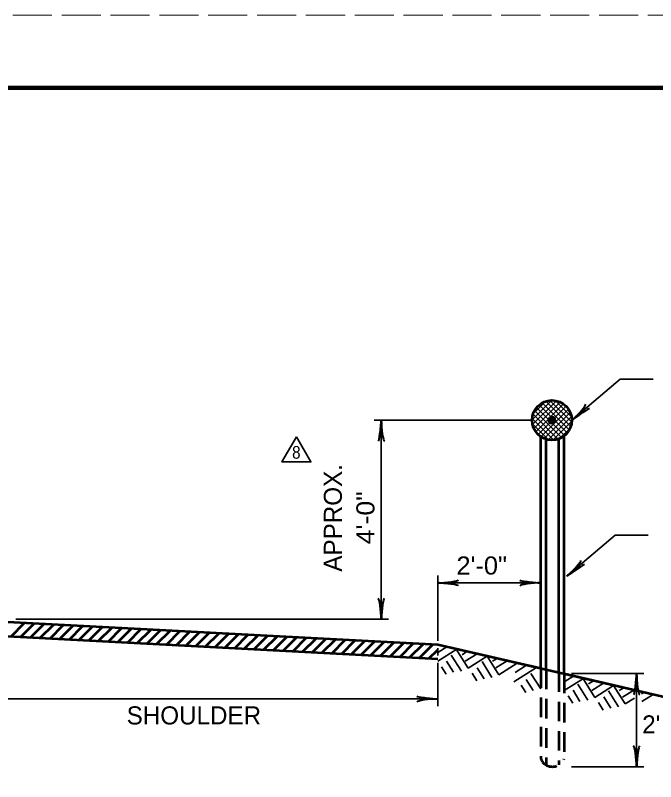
# Model space of a CAD drawing. Extents: x -54 to 626, y -41 to 399.
# Drawn here: x 87.7 to 176.2, y 292.9 to 398.7 of the extents above; entities that cross this region are included whole.
import ezdxf
from ezdxf.enums import TextEntityAlignment as Align

# ---------------------------------------------------------------- set-up
doc = ezdxf.new("R2010")
doc.units = 0
doc.header["$LTSCALE"] = 0.9
doc.linetypes.add('LONG_DASHED', pattern=[7.5, 6, -1.5])
doc.linetypes.add('MEDIUM_DASHED', pattern=[4.5, 3, -1.5])
doc.layers.add('1', color=7, linetype='Continuous', lineweight=35)
doc.layers.add('61', color=7, linetype='Continuous', lineweight=35)

msp = doc.modelspace()

# ---------------------------------------------------------------- hatches: boundary and pattern name
at = {"layer": '1'}
msp.add_hatch(color=256, dxfattribs=at).paths.add_polyline_path([(162.4069, 342.7923, 1), (161.4069, 342.7923, 1)])

# ---------------------------------------------------------------- linework, layer by layer
for p, q in [((159.1578, 342.8207), (161.8773, 345.5402)), ((159.2272, 342.1829), (162.5155, 345.4712)), ((159.3081, 343.6781), (161.022, 345.392)), ((159.4078, 341.6565), (163.0427, 345.2913)), ((159.664, 341.2056), (163.4944, 345.036)), ((164.3008, 341.4444), (160.5599, 345.1853)), ((164.5153, 341.937), (161.0512, 345.4011)), ((164.6395, 342.52), (161.6333, 345.5261)), ((164.6131, 343.2534), (162.3679, 345.4987)), ((163.2352, 340.3887), (159.5023, 344.1216)), ((163.6562, 340.6747), (159.7901, 344.5409)), ((159.9912, 340.8257), (163.8733, 344.7078)), ((164.0105, 341.0276), (160.1414, 344.8967)), ((160.3808, 340.5082), (164.1917, 344.3191)), ((163.9937, 344.58), (163.6965, 344.8772)), ((162.1532, 340.0565), (159.1721, 343.0376)), ((162.7403, 340.1766), (159.2914, 343.6254)), ((160.841, 340.2612), (164.4375, 343.8578)), ((161.3843, 340.0975), (164.6018, 343.315)), ((159.1569, 342.7923), (137.3158, 342.7923)), ((138.3158, 315.3082), (138.3158, 342.7923)), ((161.41, 340.0926), (159.2072, 342.2953)), ((162.0447, 340.0507), (164.6491, 342.6552)), ((162.9561, 340.255), (164.4476, 341.7465)), ((163.9707, 321.2404), (170.6446, 326.9158)), ((170.6446, 326.9158), (175.1863, 326.9158)), ((146.1192, 312.3259), (146.1192, 321.3259)), ((146.1192, 320.3259), (160.3523, 320.3259)), ((87.8158, 315.3082), (139.3158, 315.3082)), ((147.3964, 311.49), (146.1192, 310.6919)), ((146.1192, 311.3259), (146.1192, 310.3044)), ((148.78, 311.1706), (146.1192, 309.508)), ((148.6826, 311.1931), (150.3312, 308.5545)), ((147.9989, 310.3657), (149.3973, 308.1544)), ((150.1636, 310.8511), (149.4875, 310.4119)), ((151.5667, 310.5272), (149.9117, 309.493)), ((152.9503, 310.2077), (150.3312, 308.5545)), ((152.9503, 310.2077), (154.5541, 307.6412)), ((146.1192, 309.3044), (146.1192, 303.3044)), ((147.3347, 309.5337), (148.294, 307.9986)), ((152.2412, 309.4477), (153.6201, 307.241)), ((154.3339, 309.8882), (153.7103, 309.4986)), ((155.737, 309.5643), (154.1539, 308.5752)), ((157.1206, 309.2449), (154.5541, 307.6412)), ((146.6406, 308.7498), (147.2896, 307.7378)), ((151.577, 308.6158), (152.5362, 307.0807)), ((159.7904, 308.6285), (156.6482, 306.6651)), ((158.4067, 308.948), (156.8237, 307.9588)), ((150.8634, 307.8364), (151.5078, 306.805)), ((158.3451, 306.9917), (159.3043, 305.4566)), ((159.0093, 307.8236), (160.3523, 305.6998)), ((164.8795, 307.4537), (163.6023, 306.6556)), ((166.2631, 307.1343), (163.6023, 305.4716)), ((164.6023, 307.7896), (174.6023, 307.7896)), ((166.1657, 307.1567), (167.8144, 304.5182)), ((173.6023, 307.7896), (173.6023, 294.9441)), ((157.651, 306.2077), (158.3, 305.1958)), ((165.482, 306.3293), (166.8804, 304.1181)), ((167.6467, 306.8148), (166.9706, 306.3757)), ((169.0498, 306.4908), (167.3947, 305.4567)), ((170.4334, 306.1714), (167.8144, 304.5182)), ((170.4334, 306.1714), (172.0372, 303.6049)), ((171.817, 305.852), (171.1933, 305.4623)), ((164.8178, 305.4974), (165.7771, 303.9622)), ((169.7242, 305.4115), (171.1033, 303.2047)), ((173.2201, 305.5281), (171.637, 304.5388)), ((174.6037, 305.2087), (174.2584, 304.9929)), ((175.8899, 304.9117), (174.3067, 303.9225)), ((79.3158, 304.3044), (146.1192, 304.3044)), ((164.1238, 304.7134), (164.7728, 303.7015)), ((168.3465, 303.8001), (168.991, 302.7687)), ((169.0601, 304.5796), (170.0193, 303.0444)), ((173.3297, 304.4127), (172.0372, 303.6049)), ((164.6023, 294.9441), (174.6023, 294.9441))]:
    msp.add_line(p, q, dxfattribs=at)
at = {"layer": '1', "lineweight": 53}
for p, q in [((160.3523, 308.5399), (160.3523, 340.5239)), ((161.1023, 308.3667), (161.1023, 340.1627)), ((162.8523, 307.9627), (162.8523, 340.2099)), ((163.6023, 307.7896), (163.6023, 340.6272)), ((79.3158, 315.3082), (146.1192, 311.8259)), ((87.1213, 312.8963), (89.0269, 314.802)), ((88.4651, 312.8259), (90.3711, 314.732)), ((89.8088, 312.7555), (91.7152, 314.6619)), ((91.1526, 312.6851), (93.0593, 314.5918)), ((92.4964, 312.6147), (94.4035, 314.5217)), ((93.8402, 312.5442), (95.7477, 314.4517)), ((95.184, 312.4738), (97.0918, 314.3816)), ((146.1192, 309.8044), (79.3158, 313.3054)), ((96.5277, 312.4034), (98.4359, 314.3116)), ((97.8716, 312.3329), (99.7801, 314.2415)), ((99.2153, 312.2625), (101.1243, 314.1714)), ((100.5592, 312.1921), (102.4684, 314.1013)), ((101.9029, 312.1217), (103.8125, 314.0312)), ((103.2467, 312.0512), (105.1567, 313.9613)), ((104.5905, 311.9808), (106.5008, 313.8912)), ((105.9343, 311.9104), (107.845, 313.8211)), ((107.2781, 311.84), (109.1891, 313.751)), ((108.6219, 311.7696), (110.5332, 313.6809)), ((109.9657, 311.6992), (111.8774, 313.6109)), ((111.3094, 311.6287), (113.2216, 313.5408)), ((112.6532, 311.5582), (114.5657, 313.4708)), ((113.997, 311.4878), (115.9098, 313.4007)), ((115.3408, 311.4174), (117.254, 313.3306)), ((116.6846, 311.347), (118.5982, 313.2605)), ((118.0284, 311.2766), (119.9423, 313.1905)), ((119.3722, 311.2062), (121.2864, 313.1204)), ((120.716, 311.1357), (122.6306, 313.0503)), ((122.0597, 311.0653), (123.9748, 312.9803)), ((123.4036, 310.9949), (125.3188, 312.9102)), ((124.7473, 310.9245), (126.663, 312.8402)), ((126.0912, 310.854), (128.0072, 312.7701)), ((127.4349, 310.7836), (129.3513, 312.7)), ((128.7788, 310.7132), (130.6954, 312.6299)), ((130.1225, 310.6427), (132.0396, 312.5598)), ((131.4663, 310.5723), (133.3837, 312.4898)), ((132.8101, 310.5019), (134.7279, 312.4197)), ((134.1538, 310.4315), (136.072, 312.3497)), ((135.4977, 310.3611), (137.4162, 312.2796)), ((136.8414, 310.2907), (138.7603, 312.2095)), ((138.1852, 310.2202), (140.1045, 312.1394)), ((139.529, 310.1498), (141.4486, 312.0694)), ((140.8728, 310.0793), (142.7927, 311.9993)), ((142.2166, 310.0089), (144.1369, 311.9292)), ((143.5604, 309.9385), (145.4811, 311.8592)), ((146.1192, 311.8259), (160.3523, 308.5398)), ((146.1192, 311.8259), (175.8538, 304.9611)), ((144.9042, 309.8681), (146.1192, 311.0832))]:
    msp.add_line(p, q, dxfattribs=at)
at = {"layer": '1', "linetype": 'MEDIUM_DASHED', "lineweight": 53}
for p, q in [((160.3523, 308.5399), (160.3523, 296.0399)), ((161.1023, 308.3667), (161.1023, 295.1782)), ((162.8523, 307.9627), (162.8523, 295.1782)), ((163.6023, 307.7896), (163.6023, 296.0399))]:
    msp.add_line(p, q, dxfattribs=at)
at = {"layer": '1'}
msp.add_lwpolyline([(164.6569, 342.7923), (171.3307, 348.4677), (175.8724, 348.4677)], dxfattribs=at)
msp.add_lwpolyline([(126.5927, 340.5026), (124.5927, 337.0385), (128.5927, 337.0385)], close=True, dxfattribs=at)
at = {"layer": '1', "lineweight": 53}
msp.add_lwpolyline([(163.6023, 307.7896), (175.8538, 304.9611), (207.6092, 297.6296)], dxfattribs=at)
msp.add_circle((161.9069, 342.7923), 2.75, dxfattribs=at)
at = {"layer": '1'}
msp.add_circle((161.9069, 342.7923), 0.5, dxfattribs=at)
at = {"layer": '1', "linetype": 'MEDIUM_DASHED', "lineweight": 53}
msp.add_arc((161.9773, 296.6969), 1.7528, 202.01371, 337.98629, dxfattribs=at)
at = {"layer": '1', "lineweight": 40}
for centre, major_axis, ratio, start_param, end_param in [((165.3092, 343.7097), (-1.2592, -1.2758), 0.122415, 0.89635335, 3.14159265), ((165.3092, 343.7097), (-1.2592, -1.2758), 0.122415, 0.89635335, 3.14159265), ((165.6476, 343.357), (-1.4518, -1.0041), 0.07063, 3.14071475, 5.41810995), ((165.6476, 343.357), (-1.4518, -1.0041), 0.07063, 3.14071475, 5.41810995), ((138.1042, 341.6718), (0.1757, 1.7565), 0.07063, 3.14071475, 5.41810995), ((138.5921, 341.7011), (-0.1562, 1.7857), 0.122415, 0.89635335, 3.14159265), ((164.623, 322.1578), (-1.2592, -1.2758), 0.122415, 0.89635335, 3.14159265), ((164.623, 322.1578), (-1.2592, -1.2758), 0.122415, 0.89635335, 3.14159265), ((164.9614, 321.8051), (-1.4518, -1.0041), 0.07063, 3.14071475, 5.41810995), ((164.9614, 321.8051), (-1.4518, -1.0041), 0.07063, 3.14071475, 5.41810995), ((147.2104, 320.6022), (-1.7857, -0.1562), 0.122415, 0.89635335, 3.14159265), ((147.2104, 320.6022), (-1.7857, -0.1562), 0.122415, 0.89635335, 3.14159265), ((159.2318, 320.5375), (1.7565, -0.1757), 0.07063, 3.14071475, 5.41810995), ((147.2398, 320.1143), (-1.7565, 0.1757), 0.07063, 3.14071475, 5.41810995), ((147.2398, 320.1143), (-1.7565, 0.1757), 0.07063, 3.14071475, 5.41810995), ((159.2611, 320.0496), (1.7857, 0.1562), 0.122415, 0.89635335, 3.14159265), ((138.0395, 316.3994), (0.1562, -1.7857), 0.122415, 0.89635335, 3.14159265), ((138.5274, 316.4288), (-0.1757, -1.7565), 0.07063, 3.14071475, 5.41810995), ((173.3907, 306.6691), (0.1757, 1.7565), 0.07063, 3.14071475, 5.41810995), ((173.3907, 306.6691), (0.1757, 1.7565), 0.07063, 3.14071475, 5.41810995), ((173.8786, 306.6984), (-0.1562, 1.7857), 0.122415, 0.89635335, 3.14159265), ((173.8786, 306.6984), (-0.1562, 1.7857), 0.122415, 0.89635335, 3.14159265), ((145.0281, 304.0281), (1.7857, 0.1562), 0.122415, 0.89635335, 3.14159265), ((144.9987, 304.516), (1.7565, -0.1757), 0.07063, 3.14071475, 5.41810995), ((173.326, 296.0353), (0.1562, -1.7857), 0.122415, 0.89635335, 3.14159265), ((173.8139, 296.0646), (-0.1757, -1.7565), 0.07063, 3.14071475, 5.41810995)]:
    msp.add_ellipse(centre, major_axis=major_axis, ratio=ratio, start_param=start_param, end_param=end_param, dxfattribs=at)
at = {"layer": '61', "linetype": 'LONG_DASHED', "lineweight": 13}
msp.add_line((-54.3422, 398.7039), (625.6777, 398.7039), dxfattribs=at)
at = {"layer": '61', "lineweight": 158}
msp.add_lwpolyline([(614.6977, 388.7039), (-24.3422, 388.7039), (-24.3422, -31.3161)], dxfattribs=at)

# ---------------------------------------------------------------- texts
at = {"layer": '1'}
for s, height, width, p in [('8', 1.75, 0.9, (125.9962, 337.4754)), ('2\'-0"', 2.5, 1.05, (148.7068, 321.4764))]:
    msp.add_text(s, height=height, dxfattribs=dict(at, width=width)).set_placement(p)
msp.add_text('APPROX.', height=2.5, rotation=90, dxfattribs=at).set_placement((132.8772, 329.3046), align=Align.CENTER)
at = {"layer": '1', "width": 1.1}
msp.add_text('4\'-0"', height=2.5, rotation=90, dxfattribs=at).set_placement((137.3772, 329.3047), align=Align.CENTER)
at = {"layer": '1'}
for s, p in [('SHOULDER', (103.134, 300.7753)), ("2' MIN.", (174.3769, 299.531))]:
    msp.add_text(s, height=2.5, dxfattribs=at).set_placement(p)

doc.saveas('drawing.dxf')
